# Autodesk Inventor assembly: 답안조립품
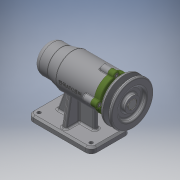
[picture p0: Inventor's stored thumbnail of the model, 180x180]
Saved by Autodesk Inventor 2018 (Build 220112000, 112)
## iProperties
Created: 2019-07
Part Number: 답안조립품
Material: 일반
Document SubType Name: Assembly
Designer: USER
Author: USER
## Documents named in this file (12)
- C:\Users\USER\Desktop\490704V1020\답안조립품.iam
- C:\Users\USER\Desktop\490704V1020\본체.ipt
- C:\Users\USER\Desktop\490704V1020\V벨트풀리.ipt
- C:\Users\USER\Desktop\490704V1020\멈춤나사 M3.ipt
- C:\Users\USER\Desktop\490704V1020\베어링 6004.ipt
- C:\Users\USER\Desktop\490704V1020\베어링 51202.ipt
- C:\Users\USER\Desktop\490704V1020\볼트 M4.ipt
- C:\Users\USER\Desktop\490704V1020\어댑터슬리브.ipt
- C:\Users\USER\Desktop\490704V1020\오일 실.ipt
- C:\Users\USER\Desktop\490704V1020\축.ipt
- C:\Users\USER\Desktop\490704V1020\커버.ipt
- C:\Users\USER\Desktop\490704V1020\키 5 x 5 x 16.ipt
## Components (1 placed, 1 different names)
1. V벨트풀리:1
